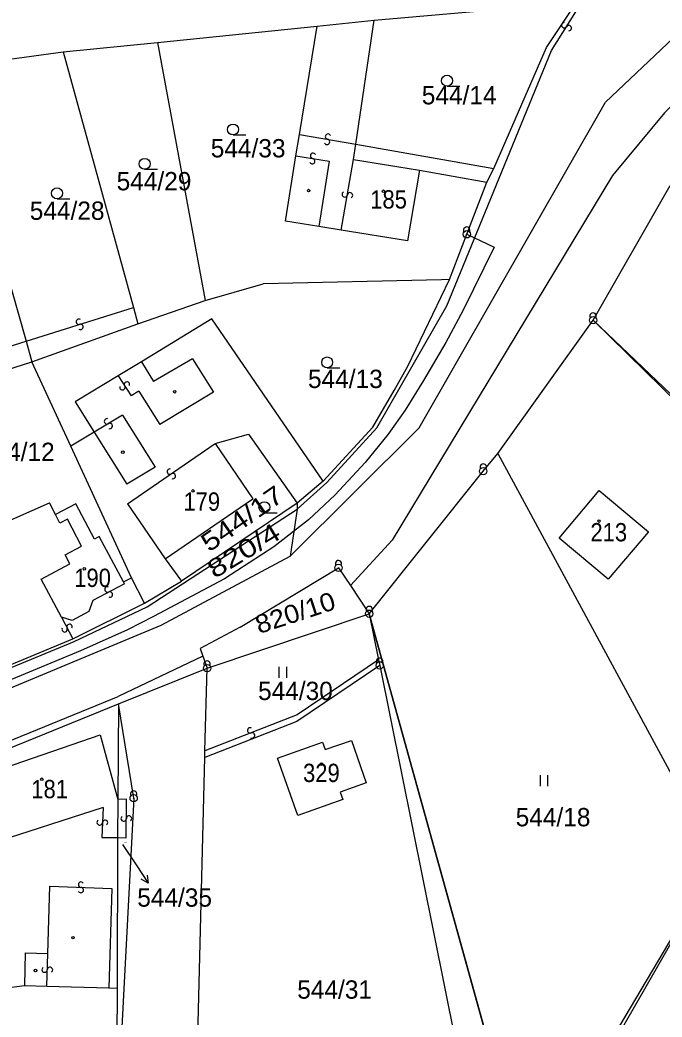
# Model space of a CAD drawing. Extents: x -680102 to -677253, y -1007548 to -1006096.
# Drawn here: x -679529.5 to -679441.7, y -1007099.8 to -1006963.5 of the extents above; entities that cross this region are included whole.
import ezdxf
from ezdxf.enums import TextEntityAlignment as Align

# ---------------------------------------------------------------- set-up
doc = ezdxf.new("R2010")
doc.units = 0
for name, color, linetype, lineweight in [('1', 7, 'Continuous', 25), ('11', 7, 'Continuous', 25), ('16', 7, 'Continuous', 25), ('24', 7, 'Continuous', 25), ('25', 7, 'Continuous', 25), ('4', 7, 'Continuous', 25)]:
    doc.layers.add(name, color=color, linetype=linetype, lineweight=lineweight)
doc.layers.add('18', color=7, linetype='Continuous')
doc.layers.add('19', color=7, linetype='Continuous')

msp = doc.modelspace()

# ---------------------------------------------------------------- linework, layer by layer
at = {"layer": '1'}
for p, q in [((-679481.01, -1006963.58), (-679453.36, -1006961.15)), ((-679457.44, -1006967.29), (-679453.36, -1006961.15)), ((-679510.65, -1006966.63), (-679488.83, -1006964.38)), ((-679491.25, -1006979.17), (-679488.83, -1006964.38)), ((-679488.83, -1006964.38), (-679481.01, -1006963.58)), ((-679483.55, -1006980.51), (-679481.01, -1006963.58)), ((-679523.55, -1006967.91), (-679510.65, -1006966.63)), ((-679464.65, -1006983.82), (-679457.44, -1006967.29)), ((-679483.55, -1006980.51), (-679464.65, -1006983.82)), ((-679474.81, -1006984.05), (-679465.62, -1006985.69)), ((-679465.62, -1006985.69), (-679464.65, -1006983.82)), ((-679468.36, -1006992.82), (-679465.62, -1006985.69)), ((-679470.74, -1006999), (-679468.36, -1006992.82)), ((-679471.81, -1006999.04), (-679496.2, -1006999.59)), ((-679470.74, -1006999), (-679471.81, -1006999.04)), ((-679513.36, -1007005.05), (-679504.12, -1007001.86)), ((-679513.94, -1007002.8), (-679513.36, -1007005.05)), ((-679527.83, -1007010.23), (-679513.36, -1007005.05)), ((-679503.2, -1007004.38), (-679512.85, -1007010.24)), ((-679488, -1007026.53), (-679503.2, -1007004.38)), ((-679451.09, -1007004.55), (-679408.88, -1007044.79)), ((-679543.18, -1007015.16), (-679527.83, -1007010.23)), ((-679522.5, -1007021.78), (-679527.83, -1007010.23)), ((-679512.85, -1007010.24), (-679516.01, -1007012.14)), ((-679516.01, -1007012.14), (-679521.9, -1007015.69)), ((-679502.77, -1007021.41), (-679498.2, -1007020.11)), ((-679498.2, -1007020.11), (-679491.56, -1007029.57)), ((-679502.77, -1007021.41), (-679497.6, -1007028.96)), ((-679464.13, -1007022.76), (-679434.03, -1007078.35)), ((-679488, -1007026.53), (-679491.56, -1007029.57)), ((-679539.69, -1007035.83), (-679525.44, -1007029.5)), ((-679524.62, -1007031.11), (-679525.44, -1007029.5)), ((-679521.84, -1007029.63), (-679524.62, -1007031.11)), ((-679519.26, -1007034.46), (-679521.84, -1007029.63)), ((-679509.59, -1007037.16), (-679497.6, -1007028.96)), ((-679491.56, -1007029.57), (-679507.38, -1007040.22)), ((-679518.61, -1007034.11), (-679519.26, -1007034.46)), ((-679515.3, -1007040.3), (-679518.61, -1007034.11)), ((-679509.59, -1007037.16), (-679507.38, -1007040.22)), ((-679512.42, -1007043.2), (-679514.19, -1007039.73)), ((-679481.69, -1007044.65), (-679460.12, -1007122.3)), ((-679536.61, -1007054.02), (-679522.23, -1007048.1)), ((-679480.26, -1007051.71), (-679491.6, -1007059.37)), ((-679480.26, -1007051.71), (-679464.89, -1007127.87)), ((-679504.16, -1007063.4), (-679503.87, -1007052.1)), ((-679516, -1007056.97), (-679516.08, -1007070.02)), ((-679491.6, -1007059.37), (-679504.18, -1007064.29)), ((-679513.91, -1007069.87), (-679516.26, -1007114.97)), ((-679528.85, -1007095.43), (-679525.79, -1007095.53)), ((-679525.79, -1007095.53), (-679517.31, -1007095.79)), ((-679517.31, -1007095.79), (-679516.18, -1007095.82)), ((-679516.18, -1007095.82), (-679516.26, -1007114.97))]:
    msp.add_line(p, q, dxfattribs=at)
for points in [[(-679510.65, -1006966.63), (-679504.12, -1007001.86), (-679496.2, -1006999.59)], [(-679539.3, -1006970.04), (-679523.55, -1006967.91), (-679513.94, -1007002.8)], [(-679539.3, -1006970.04), (-679528.63, -1007007.41), (-679527.83, -1007010.23)], [(-679474.81, -1006984.05), (-679476.45, -1006993.7), (-679485.52, -1006992.24), (-679488.59, -1006991.75), (-679493.15, -1006991.01), (-679491.72, -1006982.09), (-679491.25, -1006979.17)], [(-679464.13, -1007022.76), (-679451.09, -1007004.55), (-679440.53, -1006986.17)], [(-679468.36, -1006992.82), (-679464.63, -1006994.59), (-679468.87, -1007003.18), (-679471.22, -1007007.62), (-679474.26, -1007012.79), (-679476.78, -1007016.83), (-679479.1, -1007020.11), (-679482.26, -1007024), (-679486.35, -1007028.41), (-679489.98, -1007031.85), (-679494.75, -1007035.54), (-679501.49, -1007039.88), (-679511.21, -1007045.03), (-679514.77, -1007046.84)], [(-679488, -1007026.53), (-679481.2, -1007019.19), (-679478.3, -1007014.18), (-679476.41, -1007010.84), (-679470.74, -1006999)], [(-679521.9, -1007015.69), (-679519.3, -1007019.85), (-679522.5, -1007021.78)], [(-679515.3, -1007040.3), (-679514.19, -1007039.73), (-679522.5, -1007021.78)], [(-679481.69, -1007044.65), (-679466.11, -1007025.18), (-679464.13, -1007022.76)], [(-679499.36, -1007046.49), (-679485.9, -1007038.38), (-679484.28, -1007040.79), (-679481.69, -1007044.65)], [(-679522.23, -1007048.1), (-679512.42, -1007043.2), (-679507.38, -1007040.22)], [(-679499.36, -1007046.49), (-679504.8, -1007049.41), (-679504.43, -1007050.47), (-679503.87, -1007052.1), (-679481.69, -1007044.65)], [(-679481.69, -1007044.65), (-679480.41, -1007050.95), (-679480.26, -1007051.71)], [(-679514.77, -1007046.84), (-679521.17, -1007049.71), (-679531.18, -1007053.87), (-679573.37, -1007070.68), (-679579.96, -1007073.17), (-679587.61, -1007075.54), (-679599.28, -1007078.15)], [(-679460.12, -1007122.3), (-679434.03, -1007078.35), (-679414.32, -1007049.92)], [(-679513.91, -1007069.87), (-679516, -1007056.97), (-679503.87, -1007052.1)], [(-679567.53, -1007078.91), (-679541.32, -1007067.26), (-679516, -1007056.97)], [(-679505.88, -1007131.4), (-679504.18, -1007064.29), (-679504.16, -1007063.4)], [(-679541.32, -1007067.26), (-679544.6, -1007097.51), (-679528.85, -1007095.43)], [(-679516.08, -1007070.02), (-679516.1, -1007075.25), (-679516.18, -1007095.82)]]:
    msp.add_lwpolyline(points, dxfattribs=at)
for points in [[(-679455.71, -1007034.32), (-679450.24, -1007027.81), (-679443.5, -1007033.47), (-679449.02, -1007039.94)], [(-679494.23, -1007064.41), (-679488.07, -1007062.2), (-679487.71, -1007063.22), (-679484.14, -1007061.99), (-679482.11, -1007067.78), (-679485.65, -1007069.04), (-679485.29, -1007070.05), (-679491.46, -1007072.24)]]:
    msp.add_lwpolyline(points, close=True, dxfattribs=at)
at = {"layer": '11'}
for points in [[(-679395.73, -1007033.44), (-679408.86, -1007045.89), (-679451.09, -1007004.55)], [(-679433.94, -1007078.32), (-679459.84, -1007123.39), (-679481.69, -1007044.65)]]:
    msp.add_lwpolyline(points, dxfattribs=at)
at = {"layer": '16'}
for p, q in [((-679515.42, -1007076.18), (-679513.57, -1007078.98)), ((-679513.57, -1007078.98), (-679511.923, -1007081.487))]:
    msp.add_line(p, q, dxfattribs=at)
msp.add_lwpolyline([(-679512.055, -1007080.377), (-679511.923, -1007081.487), (-679512.89, -1007080.926)], dxfattribs=at)
at = {"layer": '24'}
for centre, radius in [((-679468.36, -1006992.82), 0.5), ((-679468.36, -1006992.82), 0.022), ((-679451.09, -1007004.55), 0.5), ((-679451.09, -1007004.55), 0.022), ((-679466.11, -1007025.18), 0.5), ((-679466.11, -1007025.18), 0.022), ((-679485.9, -1007038.38), 0.5), ((-679485.9, -1007038.38), 0.022), ((-679481.69, -1007044.65), 0.5), ((-679481.69, -1007044.65), 0.022), ((-679503.87, -1007052.1), 0.5), ((-679480.26, -1007051.71), 0.5), ((-679480.26, -1007051.71), 0.022), ((-679503.87, -1007052.1), 0.022), ((-679513.91, -1007069.87), 0.5), ((-679513.91, -1007069.87), 0.022)]:
    msp.add_circle(centre, radius, dxfattribs=at)
for centre in [(-679468.361, -1006992.257), (-679451.091, -1007003.987), (-679466.111, -1007024.617), (-679485.901, -1007037.817), (-679481.691, -1007044.087), (-679503.871, -1007051.537), (-679480.261, -1007051.147), (-679513.911, -1007069.307)]:
    msp.add_arc(centre, 0.437, 328.35109, 209.97456, dxfattribs=at)
at = {"layer": '25'}
for p, q in [((-679471.06, -1006972.58), (-679469.31, -1006972.58)), ((-679500.32, -1006979.25), (-679498.57, -1006979.25)), ((-679512.41, -1006983.94), (-679510.66, -1006983.94)), ((-679524.39, -1006987.97), (-679522.64, -1006987.97)), ((-679487.45, -1007011.07), (-679485.7, -1007011.07)), ((-679496.03, -1007030.85), (-679494.28, -1007030.85)), ((-679494.017, -1007053.405), (-679494.017, -1007051.905)), ((-679492.983, -1007053.405), (-679492.983, -1007051.905)), ((-679458.297, -1007068.225), (-679458.297, -1007066.725)), ((-679457.263, -1007068.225), (-679457.263, -1007066.725))]:
    msp.add_line(p, q, dxfattribs=at)
for centre, radius in [((-679471.06, -1006971.83), 0.75), ((-679500.32, -1006978.5), 0.75), ((-679512.41, -1006983.19), 0.75), ((-679524.39, -1006987.22), 0.75), ((-679489.98, -1006986.85), 0.175), ((-679479.75, -1006986.94), 0.175), ((-679487.45, -1007010.32), 0.75), ((-679508.3, -1007014.33), 0.175), ((-679515.39, -1007022.58), 0.175), ((-679505.8, -1007027.88), 0.175), ((-679496.03, -1007030.1), 0.75), ((-679450.27, -1007032), 0.175), ((-679520.66, -1007038.52), 0.175), ((-679488.22, -1007065.21), 0.175), ((-679526.48, -1007067.27), 0.175), ((-679522.21, -1007088.92), 0.175), ((-679527.33, -1007093.4), 0.175)]:
    msp.add_circle(centre, radius, dxfattribs=at)
for centre, radius, start, end in [((-679455.03, -1006964.251), 0.368, 94.92373, 327.30476), ((-679454.411, -1006964.651), 0.369, 274.9854, 147.34354), ((-679487.334, -1006979.478), 0.368, 27.54068, 259.66936), ((-679487.467, -1006980.202), 0.369, 207.60833, 79.51769), ((-679489.38, -1006982.098), 0.367, 28.12072, 260.59109), ((-679489.503, -1006982.823), 0.369, 208.37618, 80.38474), ((-679485.052, -1006987.364), 0.368, 117.73913, 349.67008), ((-679484.328, -1006987.497), 0.369, 297.60904, 169.68441), ((-679521.397, -1007004.759), 0.367, 54.8081, 286.95578), ((-679521.184, -1007005.463), 0.369, 234.71707, 106.99327), ((-679515.455, -1007013.722), 0.369, 159.49984, 31.39308), ((-679514.827, -1007013.337), 0.368, 339.03144, 211.66023), ((-679517.557, -1007018.372), 0.369, 68.37214, 300.16023), ((-679517.182, -1007019.006), 0.368, 248.42905, 120.75093), ((-679508.966, -1007025.235), 0.368, 71.78837, 304.0379), ((-679508.555, -1007025.847), 0.369, 251.66533, 123.7746), ((-679517.497, -1007041.361), 0.369, 64.96484, 296.91467), ((-679517.162, -1007042.017), 0.368, 244.64493, 117.19328), ((-679522.694, -1007046.451), 0.368, 335.07574, 207.40409), ((-679523.348, -1007046.788), 0.369, 155.45428, 27.13095), ((-679497.98, -1007060.595), 0.368, 58.76997, 290.64931), ((-679497.719, -1007061.283), 0.367, 238.27527, 110.90395), ((-679518.558, -1007073.17), 0.368, 124.72563, 356.51148), ((-679517.823, -1007073.209), 0.368, 304.6393, 177.03779), ((-679515.277, -1007072.633), 0.368, 126.82448, 358.91015), ((-679514.542, -1007072.649), 0.368, 306.84125, 178.97978), ((-679521.114, -1007081.673), 0.367, 35.13862, 267.5058), ((-679521.147, -1007082.408), 0.368, 215.28651, 87.35862), ((-679526.087, -1007093.286), 0.368, 125.64808, 357.81824), ((-679525.352, -1007093.315), 0.369, 305.63034, 177.80283)]:
    msp.add_arc(centre, radius, start, end, dxfattribs=at)
at = {"layer": '4'}
for p, q in [((-679471.07, -1007002.57), (-679456.78, -1006967.7)), ((-679491.25, -1006979.17), (-679483.55, -1006980.51)), ((-679483.87, -1006982.61), (-679483.55, -1006980.51)), ((-679485.52, -1006992.24), (-679483.87, -1006982.61)), ((-679483.87, -1006982.61), (-679474.81, -1006984.05)), ((-679480.67, -1007019.26), (-679471.07, -1007002.57)), ((-679512.85, -1007010.24), (-679511.21, -1007012.95)), ((-679505.86, -1007009.84), (-679511.21, -1007012.95)), ((-679505.86, -1007009.84), (-679503.01, -1007014.39)), ((-679516.01, -1007012.14), (-679514.27, -1007014.91)), ((-679513.2, -1007014.26), (-679514.27, -1007014.91)), ((-679513.2, -1007014.26), (-679510.35, -1007018.81)), ((-679503.01, -1007014.39), (-679510.35, -1007018.81)), ((-679515.44, -1007017.52), (-679519.3, -1007019.85)), ((-679519.3, -1007019.85), (-679514.85, -1007026.97)), ((-679514.75, -1007029.66), (-679502.77, -1007021.41)), ((-679514.75, -1007029.66), (-679509.59, -1007037.16)), ((-679512.08, -1007043.73), (-679491.53, -1007030.37)), ((-679491.53, -1007030.37), (-679492.51, -1007036.77)), ((-679484.28, -1007040.79), (-679478.56, -1007034.59)), ((-679515.16, -1007040.56), (-679515.3, -1007040.3)), ((-679522.06, -1007048.46), (-679512.08, -1007043.73)), ((-679523.8, -1007045.14), (-679522.23, -1007048.1)), ((-679504.43, -1007050.47), (-679516.03, -1007055.98)), ((-679480.41, -1007050.95), (-679491.55, -1007058.47)), ((-679491.55, -1007058.47), (-679504.16, -1007063.4)), ((-679514.88, -1007070.01), (-679516.08, -1007070.02)), ((-679514.93, -1007075.26), (-679514.88, -1007070.01)), ((-679518.1, -1007071.15), (-679518.28, -1007075.23)), ((-679525.65, -1007091.07), (-679525.36, -1007081.88)), ((-679528.74, -1007090.97), (-679528.85, -1007095.43)), ((-679528.74, -1007090.97), (-679525.65, -1007091.07)), ((-679525.79, -1007095.53), (-679525.65, -1007091.07))]:
    msp.add_line(p, q, dxfattribs=at)
for points in [[(-679583.52, -1007075.61), (-679568.28, -1007070.4), (-679510.15, -1007046.23), (-679492.51, -1007036.77), (-679474.86, -1007019.28), (-679449.4, -1006974.77), (-679431.68, -1006958.02), (-679426.67, -1006954.59), (-679411.66, -1006948.44), (-679396.57, -1006943.87), (-679372.18, -1006940.28), (-679288.86, -1006922.55), (-679271.84, -1006918.25), (-679261.74, -1006914.21)], [(-679401.81, -1006952.27), (-679429.3, -1006963.95), (-679441.31, -1006976.21), (-679448.41, -1006984.8), (-679478.56, -1007034.59)], [(-679456.78, -1006967.7), (-679452.66, -1006961.2), (-679453.36, -1006961.15)], [(-679491.72, -1006982.09), (-679487.16, -1006982.82), (-679488.59, -1006991.75)], [(-679558.72, -1007016.85), (-679543.69, -1007012.14), (-679528.63, -1007007.41), (-679513.94, -1007002.8)], [(-679515.44, -1007017.52), (-679510.99, -1007024.64), (-679514.85, -1007026.97)], [(-679491.56, -1007029.57), (-679491.53, -1007030.37), (-679487.48, -1007026.74), (-679480.67, -1007019.26)], [(-679515.16, -1007040.56), (-679519.5, -1007042.83), (-679520.06, -1007044.37), (-679522.3, -1007045.56), (-679523.8, -1007045.14), (-679526.56, -1007039.93), (-679522.63, -1007037.84), (-679523.29, -1007036.61), (-679521.03, -1007035.41), (-679522.98, -1007031.75), (-679524, -1007032.29), (-679524.62, -1007031.11)], [(-679560.17, -1007063.64), (-679540.39, -1007056), (-679522.06, -1007048.46)], [(-679584.28, -1007083.89), (-679541.36, -1007066.28), (-679516.03, -1007055.98)], [(-679518.1, -1007071.15), (-679533.94, -1007076.21), (-679536.91, -1007067.53), (-679518.51, -1007061.19), (-679516.08, -1007070.02)], [(-679518.28, -1007075.23), (-679516.1, -1007075.25), (-679514.93, -1007075.26)], [(-679525.36, -1007081.88), (-679516.89, -1007082.19), (-679517.31, -1007095.79)]]:
    msp.add_lwpolyline(points, dxfattribs=at)

# ---------------------------------------------------------------- texts
at = {"layer": '16'}
msp.add_text('544/35', height=2.5, dxfattribs=at).set_placement((-679513.42, -1007084.68))
at = {"layer": '18'}
for s, height, p in [('544/14', 2.5, (-679474.51, -1006975.07)), ('544/33', 2.5, (-679503.37, -1006982.31)), ('544/29', 2.5, (-679516.24, -1006986.81)), ('544/28', 2.5, (-679528.12, -1006990.84)), ('544/13', 2.5, (-679490.07, -1007013.82)), ('544/12', 2.5, (-679534.94, -1007023.79)), ('544/30', 2.5, (-679496.9, -1007056.45)), ('544/18', 2.5, (-679461.67, -1007073.7)), ('544/35', 0.1, (-679515.22, -1007075.98)), ('544/31', 2.5, (-679491.54, -1007097.25))]:
    msp.add_text(s, height=height, dxfattribs=at).set_placement(p)
at = {"layer": '18', "width": 1.25}
msp.add_text('544/17', height=2.5, rotation=34.8, dxfattribs=at).set_placement((-679503.61, -1007036.322))
at = {"layer": '18'}
for s, rotation, width, p in [('820/4', 31.4, 1.3, (-679498.207, -1007037.092)), ('820/10', 18, 1.1, (-679491.427, -1007045.708))]:
    msp.add_text(s, height=2.5, rotation=rotation, dxfattribs=dict(at, width=width)).set_placement(p, align=Align.CENTER)
at = {"layer": '19', "width": 0.9}
for s, p in [('185', (-679481.56, -1006989.3)), ('179', (-679507.11, -1007030.58)), ('213', (-679451.45, -1007034.77)), ('190', (-679522.04, -1007041)), ('181', (-679527.91, -1007069.86))]:
    msp.add_text(s, height=2.5, dxfattribs=at).set_placement(p)
msp.add_text('329', height=2.5, dxfattribs=at).set_placement((-679488.24, -1007067.65), align=Align.CENTER)

doc.saveas('drawing.dxf')
